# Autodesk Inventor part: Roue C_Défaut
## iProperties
Shininess: 64.0
Length Units: 11269
Angle Units: 11279
Time Units: 11290
Mass Units: 11283
Length Display Precision: 3
Angle Display Precision: 2
Compacted: True
Part Number: Roue C_Défaut
Document SubType Name: Modeling
Created: 2006-01
Material: Par défaut
Designer: Fricot
Density: 0.0
Volumn: 0.0
Area: 0.0
PropertySet Name: Model Information
Control State: 0
Master: False
Checked Out: False
Author: Fricot
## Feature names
1. Base1
